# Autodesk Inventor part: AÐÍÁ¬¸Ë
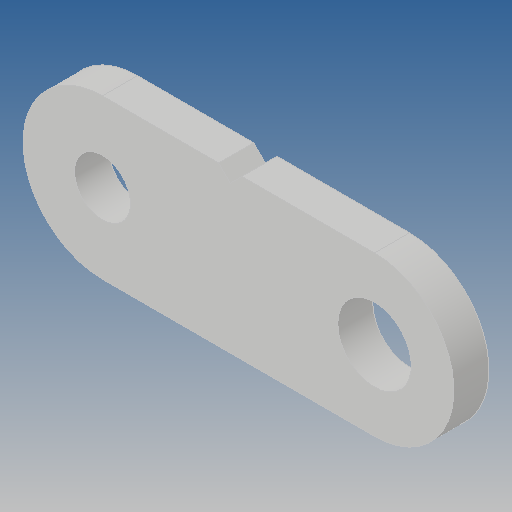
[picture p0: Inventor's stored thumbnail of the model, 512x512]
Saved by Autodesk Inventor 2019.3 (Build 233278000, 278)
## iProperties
Created: 2017-08
Part Number: AÐÍÁ¬¸Ë
Material: Ogólny
Document SubType Name: Modeling
Designer: Admin
Density: 1 g/cm^3
Appearance: Domyślna
Author: Admin
Revision Number: ÈÎºÎ
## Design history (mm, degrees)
feature "ÊäÈë1"
node "Bryła1"
